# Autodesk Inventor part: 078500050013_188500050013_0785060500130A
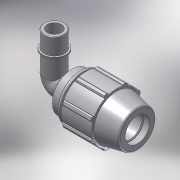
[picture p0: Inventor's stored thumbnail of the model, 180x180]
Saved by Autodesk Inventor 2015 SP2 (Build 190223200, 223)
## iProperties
Created: 2017-02
Part Number: 078500050013_188500050013_0785060500130A
Material: PVC-Piping
Description: PLASSON 90° ELBOW MALE ADAPTOR 50-1.1/4"
Document SubType Name: Modeling
Designer: KIM
Mass: 92.6774 g
Surface Area: 199.44 cm^2
Volume: 66.1981 cm^3
Density: 1.4 g/cm^3
Appearance: Smooth - White
Author: KIM
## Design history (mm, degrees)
derived "07850.ipt"
feature "Solid1::07850.ipt"
tag "TaggingFeature1"
body "Solid1"
other parameters: "d4" = 12, "d5" = 36, "d7" = 96, "d9" = 20.57143, "d11" = 4.8, "d13" = 120 deg, "d15" = 12 deg, "d16" = 83.52, "d18" = 2.5, "d19" = 35 deg, "d20" = 17.5 deg, "d21" = 89.28, "d23" = 0, "d25" = 360 deg, "d27" = 1.92, "d33" = 1, "d42" = 53.28, "d43" = 2.88, "d46" = 1.5, "d51" = 144, "d68" = 4.8, "d72" = 74, "d73" = 41.91, "d74" = 22, "d75" = 48.1965, "d76" = 29.337, "d77" = 24.2, "d79" = 16.764, "d80" = 1.2573, "d83" = 0, "d84" = 0, "d91" = 72, "d93" = 93, "d94" = 41.91, "d95" = 29.337, "d96" = 14.4, "d97" = 50 deg, "E_" = 96, "A_" = 144, "l_" = 93, "l_2" = 22, "A_1" = 74, "R_" = 41.91
